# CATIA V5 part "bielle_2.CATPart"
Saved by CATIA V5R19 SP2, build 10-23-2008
Part number: bielle_2
Bounding box of the stored display mesh (mm): x 0 to 10, y -360 to 10, z -10 to 10
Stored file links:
  C:\Users\Guillaume\Desktop\ETUDES\IFMA\S3\IAO\Projet IAO\ggaubert_1504\bielle_2.CATPart
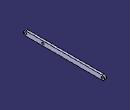
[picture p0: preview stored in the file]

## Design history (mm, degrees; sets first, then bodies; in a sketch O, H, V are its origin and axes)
Parameters
  entraxe_total_bielle_2 = 350 mm
  entraxe_bielle_12 = 80 mm
Body1 (main body)
  Sketch1 on yz-plane, origin (0, 0, 0), H (0, 1, 0), V (0, 0, 1)
    line L1 (-350, 10) -> (0, 10)
    arc A1 centre (0, 0) radius 10 from (0, 10) to (0, -10) cw
    point P3 (0, 0)
    line L2 (0, -10) -> (-350, -10)
    arc A2 centre (-350, 0) radius 10 from (-350, -10) to (-350, 10) cw
    point P6 (-350, 0)
    distance L1 L2 = 20
    distance P3 P6 = 350 {= entraxe_total_bielle_2}
    horizontal: L1 H
    tangency: A1 L1, L2 A1, A2 L1, A2 L2
    coincidence: P3 O
  Sketch2 on yz-plane, origin (0, 0, 0), H (0, 1, 0), V (0, 0, 1)
    circle A1 centre (-350, 0) radius 5
    point P1 (-350, 0)
    circle A2 centre (-270, 0) radius 5
    point P2 (-270, 0)
    circle A3 centre (0, 0) radius 5
    point P3 (0, -5)
    distance P1 O = 350 {= entraxe_total_bielle_2}
    distance P2 P1 = 80 {= entraxe_bielle_12}
    radius A2 = 5
    radius A1 = 5
    radius A3 = 5
    coincidence: P1 H, P2 H, A3 P3, P3 V
  Pad1: profile Sketch1, direction (1, 0, 0), length 10
  Pocket1: profile Sketch2, direction (-1, 0, 0), up to end face of Pad1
